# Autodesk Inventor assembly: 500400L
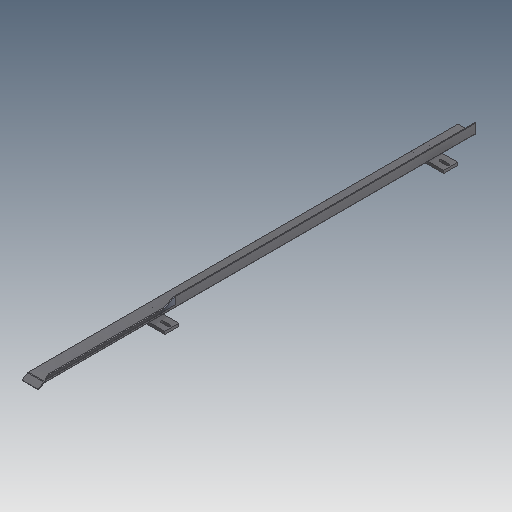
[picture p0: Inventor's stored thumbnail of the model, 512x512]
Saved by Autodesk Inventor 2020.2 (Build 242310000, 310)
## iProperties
Created: 2000-01
Part Number: 500400L
Description: WMT-CP,SS,XX,GUIDE,ANGLE
Document SubType Name: Assembly
Designer: sspink
Mass: 1283.13 g
Surface Area: 3368.18 cm^2
Volume: 548.396 cm^3
Density: 2.33979 g/cm^3
Control State: 0
Checked Out: False
Master: False
Shininess: 0.0
Length Units: 11269
Angle Units: 11279
Time Units: 11290
Mass Units: 11283
Length Display Precision: 3
Angle Display Precision: 2
Compacted: True
Dimensions: 50,1x1548,7x114 mm
Mass: 1,283 kg
DocNumber: 500400L.iam
Folder: 01 - Themengebiete\Simplification\01 - Packaging machine\
VDS_Category: 3D Komponenten
Density: 0.0
Volumn: 0.0
Area: 0.0
PropertySet Name: Model Information
Author: sspink
Revision Number: -
Title: rail
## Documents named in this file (4)
- D:\07 - DEMODATEN\OTX 2019 - Dataset - UPDATE - Dez2019\Designs\07-Packing machine\500400L.iam
- D:\07 - DEMODATEN\OTX 2019 - Dataset - UPDATE - Dez2019\Designs\07-Packing machine\Parts\ADSK-011379.ipt
- D:\07 - DEMODATEN\OTX 2019 - Dataset - UPDATE - Dez2019\Designs\07-Packing machine\Parts\ADSK-011381.ipt
- D:\07 - DEMODATEN\OTX 2019 - Dataset - UPDATE - Dez2019\Designs\07-Packing machine\Parts\ADSK-011363.ipt
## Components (4 placed, 3 different names)
1. ADSK-011379:1 — Passend:6, Fluchtend:8, Fluchtend:9, Passend:7, Fluchtend:10, Passend:8, Passend:9, Passend:10, Passend:11
2. ADSK-011381:1 — Passend:8, Passend:9, Passend:10, Passend:11
3. ADSK-011363:3 — Passend:7, Fluchtend:10, Fluchtend:11
4. ADSK-011363:4 — Passend:6, Fluchtend:8, Fluchtend:9, Fluchtend:11
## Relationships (10: Mate 6, Flush 4)
- Passend:6 [Mate]: ADSK-011379:1 ↔ ADSK-011363:4
- Fluchtend:8 [Flush]: ADSK-011379:1 ↔ ADSK-011363:4
- Fluchtend:9 [Flush]: ADSK-011379:1 ↔ ADSK-011363:4
- Passend:7 [Mate]: ADSK-011379:1 ↔ ADSK-011363:3
- Fluchtend:10 [Flush]: ADSK-011379:1 ↔ ADSK-011363:3
- Fluchtend:11 [Flush]: ADSK-011363:3 ↔ ADSK-011363:4
- Passend:8 [Mate]: ADSK-011379:1 ↔ ADSK-011381:1
- Passend:9 [Mate]: ADSK-011379:1 ↔ ADSK-011381:1
- Passend:10 [Mate]: ADSK-011379:1 ↔ ADSK-011381:1
- Passend:11 [Mate]: ADSK-011379:1 ↔ ADSK-011381:1
